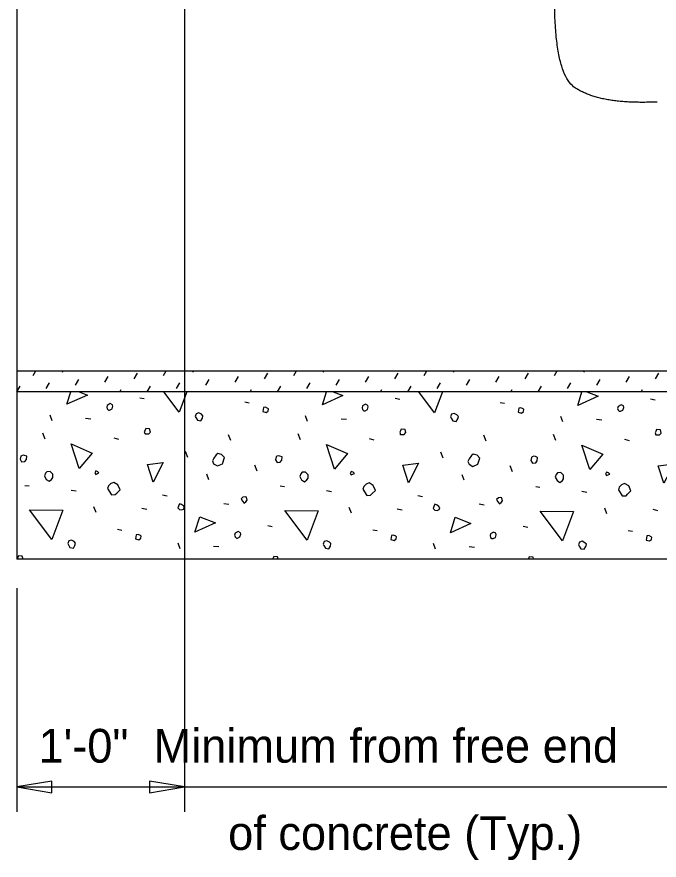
# Model space of a CAD drawing. Extents: x 110341.7 to 110413.5, y 110387.3 to 110417.8.
# Drawn here: x 110344.58 to 110348.41, y 110400.92 to 110405.96 of the extents above; entities that cross this region are included whole.
import ezdxf

# ---------------------------------------------------------------- set-up
doc = ezdxf.new("R2010")
doc.units = 0
for name, color, linetype in [('Border', 7, 'Continuous'), ('CL_Major', 7, 'Continuous'), ('Patterning', 7, 'Continuous'), ('PlotBorder_dp', 7, 'Continuous'), ('SheetBorder_dp', 7, 'Continuous')]:
    doc.layers.add(name, color=color, linetype=linetype)

msp = doc.modelspace()

# ---------------------------------------------------------------- linework, layer by layer
at = {"layer": 'Border'}
for p, q in [((110344.5778, 110402.5451), (110344.5778, 110401.2111)), ((110344.5778, 110401.3591), (110349.3523, 110401.3591)), ((110345.5778, 110401.3591), (110345.5778, 110401.2111))]:
    msp.add_line(p, q, dxfattribs=at)
for points in [[(110344.5778, 110401.3591), (110344.7861, 110401.3238), (110344.7861, 110401.3944)], [(110345.5778, 110401.3592), (110345.3696, 110401.3944), (110345.3696, 110401.3239)]]:
    msp.add_lwpolyline(points, close=True, dxfattribs=at)
msp.add_open_spline([(110348.3978, 110405.4486), (110348.0551, 110405.4333), (110347.7577, 110405.6365), (110347.7928, 110406.307)], degree=2, dxfattribs=at)
at = {"layer": 'CL_Major'}
msp.add_line((110345.5778, 110415.4617), (110345.5778, 110401.2111), dxfattribs=at)
at = {"layer": 'Patterning'}
for p, q in [((110344.675, 110403.8158), (110344.6911, 110403.8435)), ((110344.8501, 110403.8352), (110344.8549, 110403.8435)), ((110345.4529, 110403.8158), (110345.4689, 110403.8435)), ((110345.6279, 110403.8352), (110345.6327, 110403.8435)), ((110346.2307, 110403.8158), (110346.2467, 110403.8435)), ((110346.4057, 110403.8352), (110346.4105, 110403.8435)), ((110347.0085, 110403.8158), (110347.0246, 110403.8435)), ((110347.1835, 110403.8352), (110347.1883, 110403.8435)), ((110347.7863, 110403.8158), (110347.8024, 110403.8435)), ((110347.9613, 110403.8352), (110347.9661, 110403.8435)), ((110344.9278, 110403.7574), (110344.9473, 110403.791)), ((110345.1028, 110403.7769), (110345.1223, 110403.8105)), ((110345.2779, 110403.7963), (110345.2973, 110403.8299)), ((110345.7057, 110403.7574), (110345.7251, 110403.791)), ((110345.8807, 110403.7769), (110345.9001, 110403.8105)), ((110346.0557, 110403.7963), (110346.0751, 110403.8299)), ((110346.4835, 110403.7574), (110346.5029, 110403.791)), ((110346.6585, 110403.7769), (110346.6779, 110403.8105)), ((110346.8335, 110403.7963), (110346.8529, 110403.8299)), ((110347.2613, 110403.7574), (110347.2807, 110403.791)), ((110347.4363, 110403.7769), (110347.4557, 110403.8105)), ((110347.6113, 110403.7963), (110347.6308, 110403.8299)), ((110348.0391, 110403.7574), (110348.0586, 110403.791)), ((110348.2141, 110403.7769), (110348.2336, 110403.8105)), ((110348.3891, 110403.7963), (110348.4086, 110403.8299)), ((110344.5778, 110403.7185), (110344.5973, 110403.7521)), ((110344.7528, 110403.738), (110344.7723, 110403.7716)), ((110345.1919, 110403.7185), (110345.2001, 110403.7327)), ((110345.3556, 110403.7185), (110345.3751, 110403.7521)), ((110345.5306, 110403.738), (110345.5501, 110403.7716)), ((110345.9697, 110403.7185), (110345.9779, 110403.7327)), ((110346.1335, 110403.7185), (110346.1529, 110403.7521)), ((110346.3085, 110403.738), (110346.3279, 110403.7716)), ((110346.7475, 110403.7185), (110346.7557, 110403.7327)), ((110346.9113, 110403.7185), (110346.9307, 110403.7521)), ((110347.0863, 110403.738), (110347.1057, 110403.7716)), ((110347.5253, 110403.7185), (110347.5335, 110403.7327)), ((110347.6891, 110403.7185), (110347.7085, 110403.7521)), ((110347.8641, 110403.738), (110347.8835, 110403.7716)), ((110348.3032, 110403.7185), (110348.3113, 110403.7327)), ((110345.3116, 110403.6832), (110345.3382, 110403.6779)), ((110345.9374, 110403.6584), (110345.9639, 110403.6531)), ((110346.8355, 110403.6797), (110346.862, 110403.6744)), ((110347.4612, 110403.6549), (110347.4878, 110403.6496)), ((110348.3593, 110403.6761), (110348.3858, 110403.6708)), ((110344.7884, 110403.5453), (110344.776, 110403.5789)), ((110344.9881, 110403.5612), (110345.02, 110403.5577)), ((110346.3122, 110403.5418), (110346.2998, 110403.5754)), ((110346.5119, 110403.5577), (110346.5438, 110403.5541)), ((110347.836, 110403.5382), (110347.8236, 110403.5718)), ((110348.0358, 110403.5541), (110348.0676, 110403.5506)), ((110344.746, 110403.4357), (110344.7318, 110403.4711)), ((110345.1561, 110403.4428), (110345.1844, 110403.4357)), ((110345.8543, 110403.4269), (110345.8402, 110403.4622)), ((110346.2698, 110403.4322), (110346.2556, 110403.4675)), ((110346.6799, 110403.4392), (110346.7082, 110403.4322)), ((110347.3782, 110403.4233), (110347.364, 110403.4587)), ((110347.7936, 110403.4286), (110347.7794, 110403.464)), ((110348.2037, 110403.4357), (110348.232, 110403.4286)), ((110345.598, 110403.3261), (110345.5839, 110403.3615)), ((110347.1218, 110403.3226), (110347.1077, 110403.3579)), ((110346.0117, 110403.2448), (110345.9975, 110403.2801)), ((110347.5355, 110403.2413), (110347.5213, 110403.2766)), ((110345.7235, 110403.1935), (110345.7112, 110403.2271)), ((110347.2473, 110403.19), (110347.235, 110403.2236)), ((110344.6257, 110403.1599), (110344.6505, 110403.1564)), ((110344.9015, 110403.1317), (110344.9316, 110403.1263)), ((110346.1496, 110403.1564), (110346.1743, 110403.1529)), ((110346.4253, 110403.1281), (110346.4554, 110403.1228)), ((110347.6734, 110403.1529), (110347.6981, 110403.1493)), ((110345.446, 110403.1034), (110345.4743, 110403.0963)), ((110346.9698, 110403.0998), (110346.9981, 110403.0928)), ((110347.9491, 110403.1246), (110347.9792, 110403.1193)), ((110345.05, 110402.9973), (110345.0376, 110403.0309)), ((110345.8119, 110403.0521), (110345.842, 110403.0468)), ((110346.5738, 110402.9938), (110346.5614, 110403.0274)), ((110347.3357, 110403.0486), (110347.3658, 110403.0433)), ((110345.324, 110403.0238), (110345.3523, 110403.0167)), ((110346.8478, 110403.0203), (110346.8761, 110403.0132)), ((110348.0976, 110402.9902), (110348.0853, 110403.0238)), ((110348.3716, 110403.0167), (110348.3999, 110403.0097)), ((110344.5778, 110402.9178), (110344.578, 110402.9178)), ((110345.1773, 110402.8983), (110345.2038, 110402.893)), ((110346.0753, 110402.9195), (110346.1018, 110402.9142)), ((110346.7011, 110402.8948), (110346.7276, 110402.8895)), ((110347.5991, 110402.916), (110347.6256, 110402.9107)), ((110348.2249, 110402.8912), (110348.2514, 110402.8859)), ((110345.5521, 110402.7816), (110345.5397, 110402.8152)), ((110345.7518, 110402.7975), (110345.7836, 110402.794)), ((110347.0759, 110402.7781), (110347.0635, 110402.8117)), ((110347.2756, 110402.794), (110347.3074, 110402.7905))]:
    msp.add_line(p, q, dxfattribs=at)
for points in [[(110344.8768, 110403.6443), (110344.8996, 110403.7185)], [(110344.9497, 110403.7185), (110344.9987, 110403.6991), (110344.8768, 110403.6443)], [(110345.5467, 110403.5966), (110345.454, 110403.7185)], [(110345.5923, 110403.7185), (110345.5467, 110403.5966)], [(110346.4006, 110403.6408), (110346.4245, 110403.7185)], [(110346.4646, 110403.7185), (110346.5226, 110403.6956), (110346.4006, 110403.6408)], [(110347.0706, 110403.593), (110346.9752, 110403.7185)], [(110347.1175, 110403.7185), (110347.0706, 110403.593)], [(110347.9244, 110403.6372), (110347.9494, 110403.7185)], [(110347.9794, 110403.7185), (110348.0464, 110403.692), (110347.9244, 110403.6372)], [(110345.1243, 110403.6089), (110345.1313, 110403.6089), (110345.1455, 110403.616), (110345.1508, 110403.6319), (110345.149, 110403.6408), (110345.1349, 110403.6478), (110345.1172, 110403.6372), (110345.1136, 110403.6266), (110345.1172, 110403.616), (110345.1243, 110403.6089)], [(110346.6481, 110403.6054), (110346.6551, 110403.6054), (110346.6693, 110403.6125), (110346.6746, 110403.6284), (110346.6728, 110403.6372), (110346.6587, 110403.6443), (110346.641, 110403.6337), (110346.6375, 110403.6231), (110346.641, 110403.6125), (110346.6481, 110403.6054)], [(110348.1719, 110403.6019), (110348.179, 110403.6019), (110348.1931, 110403.6089), (110348.1984, 110403.6249), (110348.1966, 110403.6337), (110348.1825, 110403.6408), (110348.1648, 110403.6302), (110348.1613, 110403.6196), (110348.1648, 110403.6089), (110348.1719, 110403.6019)], [(110345.6457, 110403.5648), (110345.6546, 110403.5488), (110345.6758, 110403.5453), (110345.6846, 110403.5612), (110345.6882, 110403.5754), (110345.6793, 110403.5842), (110345.6634, 110403.593), (110345.6475, 110403.5877), (110345.6422, 110403.5718), (110345.6457, 110403.5648)], [(110346.0453, 110403.6001), (110346.0647, 110403.5948), (110346.0771, 110403.6036), (110346.0788, 110403.616), (110346.0753, 110403.6196), (110346.0612, 110403.6266), (110346.0488, 110403.6249), (110346.047, 110403.6125), (110346.0453, 110403.6001)], [(110347.1696, 110403.5612), (110347.1784, 110403.5453), (110347.1996, 110403.5418), (110347.2085, 110403.5577), (110347.212, 110403.5718), (110347.2031, 110403.5807), (110347.1872, 110403.5895), (110347.1713, 110403.5842), (110347.166, 110403.5683), (110347.1696, 110403.5612)], [(110347.5691, 110403.5966), (110347.5885, 110403.5913), (110347.6009, 110403.6001), (110347.6027, 110403.6125), (110347.5991, 110403.616), (110347.585, 110403.6231), (110347.5726, 110403.6213), (110347.5708, 110403.6089), (110347.5691, 110403.5966)], [(110345.3435, 110403.4675), (110345.3647, 110403.4675), (110345.3753, 110403.4781), (110345.37, 110403.4976), (110345.347, 110403.4993), (110345.3435, 110403.4887), (110345.3382, 110403.4799), (110345.3435, 110403.4675), (110345.3399, 110403.4711)], [(110346.8673, 110403.464), (110346.8885, 110403.464), (110346.8991, 110403.4746), (110346.8938, 110403.494), (110346.8708, 110403.4958), (110346.8673, 110403.4852), (110346.862, 110403.4764), (110346.8673, 110403.464), (110346.8637, 110403.4675)], [(110348.3911, 110403.4605), (110348.4123, 110403.4605), (110348.4229, 110403.4711), (110348.4176, 110403.4905), (110348.3946, 110403.4923), (110348.3911, 110403.4817), (110348.3858, 110403.4728), (110348.3911, 110403.4605), (110348.3876, 110403.464)], [(110344.9492, 110403.2607), (110344.9015, 110403.4074), (110345.027, 110403.3526), (110344.9492, 110403.2607)], [(110346.4731, 110403.2572), (110346.4253, 110403.4039), (110346.5508, 110403.3491), (110346.4731, 110403.2572)], [(110347.9969, 110403.2536), (110347.9491, 110403.4004), (110348.0747, 110403.3456), (110347.9969, 110403.2536)], [(110344.5975, 110403.3155), (110344.6063, 110403.2996), (110344.6257, 110403.3014), (110344.6346, 110403.3137), (110344.6363, 110403.3332), (110344.624, 110403.3385), (110344.6151, 110403.3402), (110344.6045, 110403.3367), (110344.601, 110403.3332), (110344.5975, 110403.3155)], [(110345.7518, 110403.289), (110345.7748, 110403.2766), (110345.8048, 110403.289), (110345.8172, 110403.3261), (110345.7995, 110403.3438), (110345.7766, 110403.3491), (110345.766, 110403.342), (110345.7536, 110403.3226), (110345.7447, 110403.3067), (110345.7518, 110403.289)], [(110346.1213, 110403.312), (110346.1301, 110403.2961), (110346.1496, 110403.2978), (110346.1584, 110403.3102), (110346.1602, 110403.3296), (110346.1478, 110403.3349), (110346.139, 110403.3367), (110346.1283, 110403.3332), (110346.1248, 110403.3296), (110346.1213, 110403.312)], [(110347.2756, 110403.2854), (110347.2986, 110403.2731), (110347.3287, 110403.2854), (110347.341, 110403.3226), (110347.3234, 110403.3402), (110347.3004, 110403.3456), (110347.2898, 110403.3385), (110347.2774, 110403.319), (110347.2686, 110403.3031), (110347.2756, 110403.2854)], [(110347.6451, 110403.3084), (110347.6539, 110403.2925), (110347.6734, 110403.2943), (110347.6822, 110403.3067), (110347.684, 110403.3261), (110347.6716, 110403.3314), (110347.6628, 110403.3332), (110347.6522, 110403.3296), (110347.6486, 110403.3261), (110347.6451, 110403.3084)], [(110345.3912, 110403.1794), (110345.3576, 110403.2837), (110345.4513, 110403.2961), (110345.3912, 110403.1794)], [(110346.915, 110403.1758), (110346.8814, 110403.2801), (110346.9751, 110403.2925), (110346.915, 110403.1758)], [(110348.4388, 110403.1723), (110348.4052, 110403.2766), (110348.4989, 110403.289), (110348.4388, 110403.1723)], [(110344.7424, 110403.2165), (110344.753, 110403.1953), (110344.7707, 110403.1847), (110344.7848, 110403.1953), (110344.7919, 110403.2059), (110344.7919, 110403.2271), (110344.776, 110403.243), (110344.7566, 110403.2413), (110344.7477, 110403.2324), (110344.7424, 110403.2165)], [(110345.0482, 110403.2253), (110345.0677, 110403.2342), (110345.0606, 110403.2413), (110345.0482, 110403.2466), (110345.0429, 110403.2342), (110345.0482, 110403.2253)], [(110346.2662, 110403.213), (110346.2768, 110403.1918), (110346.2945, 110403.1811), (110346.3087, 110403.1918), (110346.3157, 110403.2024), (110346.3157, 110403.2236), (110346.2998, 110403.2395), (110346.2804, 110403.2377), (110346.2715, 110403.2289), (110346.2662, 110403.213)], [(110346.5721, 110403.2218), (110346.5915, 110403.2306), (110346.5844, 110403.2377), (110346.5721, 110403.243), (110346.5668, 110403.2306), (110346.5721, 110403.2218)], [(110347.79, 110403.2094), (110347.8007, 110403.1882), (110347.8183, 110403.1776), (110347.8325, 110403.1882), (110347.8395, 110403.1988), (110347.8395, 110403.22), (110347.8236, 110403.2359), (110347.8042, 110403.2342), (110347.7953, 110403.2253), (110347.79, 110403.2094)], [(110348.0959, 110403.2183), (110348.1153, 110403.2271), (110348.1082, 110403.2342), (110348.0959, 110403.2395), (110348.0906, 110403.2271), (110348.0959, 110403.2183)], [(110345.1189, 110403.1405), (110345.1419, 110403.1034), (110345.1649, 110403.1051), (110345.1738, 110403.114), (110345.1932, 110403.1334), (110345.1808, 110403.1635), (110345.1561, 110403.1776), (110345.1384, 110403.1705), (110345.1243, 110403.1564), (110345.1189, 110403.1405)], [(110346.6428, 110403.137), (110346.6657, 110403.0998), (110346.6887, 110403.1016), (110346.6976, 110403.1104), (110346.717, 110403.1299), (110346.7046, 110403.1599), (110346.6799, 110403.1741), (110346.6622, 110403.167), (110346.6481, 110403.1529), (110346.6428, 110403.137)], [(110348.1666, 110403.1334), (110348.1896, 110403.0963), (110348.2125, 110403.0981), (110348.2214, 110403.1069), (110348.2408, 110403.1263), (110348.2285, 110403.1564), (110348.2037, 110403.1705), (110348.186, 110403.1635), (110348.1719, 110403.1493), (110348.1666, 110403.1334)], [(110345.9233, 110403.0645), (110345.9339, 110403.0539), (110345.9445, 110403.0609), (110345.9516, 110403.0715), (110345.948, 110403.0892), (110345.9392, 110403.091), (110345.9268, 110403.0892), (110345.9162, 110403.0786), (110345.9233, 110403.0645)], [(110347.4471, 110403.0609), (110347.4577, 110403.0503), (110347.4683, 110403.0574), (110347.4754, 110403.068), (110347.4718, 110403.0857), (110347.463, 110403.0875), (110347.4506, 110403.0857), (110347.44, 110403.0751), (110347.4471, 110403.0609)], [(110345.5485, 110403.015), (110345.5609, 110403.0132), (110345.5733, 110403.0185), (110345.5768, 110403.0291), (110345.5715, 110403.038), (110345.5609, 110403.045), (110345.5485, 110403.0503), (110345.5414, 110403.0362), (110345.5379, 110403.0256), (110345.5485, 110403.015)], [(110347.0723, 110403.0114), (110347.0847, 110403.0097), (110347.0971, 110403.015), (110347.1006, 110403.0256), (110347.0953, 110403.0344), (110347.0847, 110403.0415), (110347.0723, 110403.0468), (110347.0653, 110403.0327), (110347.0617, 110403.022), (110347.0723, 110403.0114)], [(110344.7866, 110402.8364), (110344.6523, 110403.0132), (110344.852, 110403.0114), (110344.7866, 110402.8364)], [(110346.3104, 110402.8329), (110346.1761, 110403.0097), (110346.3758, 110403.0079), (110346.3104, 110402.8329)], [(110347.8342, 110402.8294), (110347.6999, 110403.0061), (110347.8996, 110403.0044), (110347.8342, 110402.8294)], [(110345.6404, 110402.8806), (110345.6687, 110402.9726), (110345.7624, 110402.9354), (110345.6404, 110402.8806)], [(110347.1643, 110402.8771), (110347.1925, 110402.969), (110347.2862, 110402.9319), (110347.1643, 110402.8771)], [(110345.8879, 110402.8453), (110345.895, 110402.8453), (110345.9091, 110402.8523), (110345.9144, 110402.8683), (110345.9127, 110402.8771), (110345.8985, 110402.8842), (110345.8809, 110402.8736), (110345.8773, 110402.8629), (110345.8809, 110402.8523), (110345.8879, 110402.8453)], [(110347.4117, 110402.8417), (110347.4188, 110402.8417), (110347.433, 110402.8488), (110347.4383, 110402.8647), (110347.4365, 110402.8736), (110347.4223, 110402.8806), (110347.4047, 110402.87), (110347.4011, 110402.8594), (110347.4047, 110402.8488), (110347.4117, 110402.8417)], [(110344.8856, 110402.8046), (110344.8944, 110402.7887), (110344.9157, 110402.7852), (110344.9245, 110402.8011), (110344.928, 110402.8152), (110344.9192, 110402.8241), (110344.9033, 110402.8329), (110344.8874, 110402.8276), (110344.8821, 110402.8117), (110344.8856, 110402.8046)], [(110345.2851, 110402.84), (110345.3046, 110402.8347), (110345.3169, 110402.8435), (110345.3187, 110402.8559), (110345.3152, 110402.8594), (110345.301, 110402.8665), (110345.2887, 110402.8647), (110345.2869, 110402.8523), (110345.2851, 110402.84)], [(110346.4094, 110402.8011), (110346.4183, 110402.7852), (110346.4395, 110402.7816), (110346.4483, 110402.7975), (110346.4518, 110402.8117), (110346.443, 110402.8205), (110346.4271, 110402.8294), (110346.4112, 110402.8241), (110346.4059, 110402.8081), (110346.4094, 110402.8011)], [(110346.8089, 110402.8364), (110346.8284, 110402.8311), (110346.8408, 110402.84), (110346.8425, 110402.8523), (110346.839, 110402.8559), (110346.8248, 110402.8629), (110346.8125, 110402.8612), (110346.8107, 110402.8488), (110346.8089, 110402.8364)], [(110347.9332, 110402.7975), (110347.9421, 110402.7816), (110347.9633, 110402.7781), (110347.9721, 110402.794), (110347.9757, 110402.8081), (110347.9668, 110402.817), (110347.9509, 110402.8258), (110347.935, 110402.8205), (110347.9297, 110402.8046), (110347.9332, 110402.7975)], [(110348.3327, 110402.8329), (110348.3522, 110402.8276), (110348.3646, 110402.8364), (110348.3663, 110402.8488), (110348.3628, 110402.8523), (110348.3487, 110402.8594), (110348.3363, 110402.8576), (110348.3345, 110402.8453), (110348.3327, 110402.8329)], [(110344.615, 110402.7185), (110344.6098, 110402.7374), (110344.5869, 110402.7392), (110344.5833, 110402.7286), (110344.578, 110402.7198), (110344.5785, 110402.7185)], [(110346.1378, 110402.7185), (110346.1336, 110402.7339), (110346.1107, 110402.7357), (110346.1071, 110402.7251), (110346.1032, 110402.7185)], [(110347.6607, 110402.7185), (110347.6575, 110402.7304), (110347.6345, 110402.7321), (110347.6309, 110402.7215), (110347.6291, 110402.7185)]]:
    msp.add_lwpolyline(points, dxfattribs=at)
at = {"layer": 'PlotBorder_dp'}
for p, q in [((110344.5778, 110406.0935), (110344.5778, 110402.7185)), ((110344.5778, 110403.8435), (110356.9648, 110403.8435)), ((110356.9648, 110403.7185), (110344.5778, 110403.7185)), ((110356.9648, 110402.7185), (110344.5778, 110402.7185))]:
    msp.add_line(p, q, dxfattribs=at)

# ---------------------------------------------------------------- texts
at = {"layer": 'SheetBorder_dp'}
for s, p in [('1\'-0"  Minimum from free end ', (110344.7068, 110401.5042)), ('of concrete (Typ.)', (110345.8383, 110400.9829))]:
    msp.add_text(s, height=0.2016, dxfattribs=at).set_placement(p)

doc.saveas('drawing.dxf')
